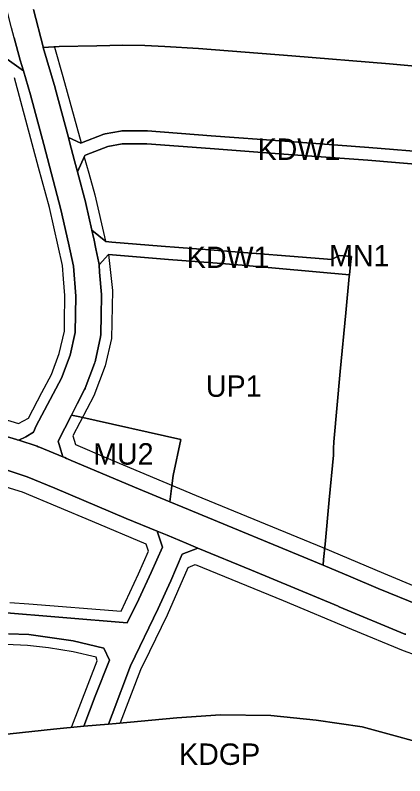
# Model space of a CAD drawing. Extents: x -284239 to -281592, y 34477 to 37267.
# Drawn here: x -282241.7 to -282059.7, y 34820.9 to 35175.9 of the extents above; entities that cross this region are included whole.
import ezdxf

# ---------------------------------------------------------------- set-up
doc = ezdxf.new("R2010")
doc.units = 0
for name, color, linetype in [('linie_rozgraniczajace', 7, 'Continuous'), ('linie_zabudowy_nieprzekraczalne', 7, 'Continuous'), ('oznaczenia_przeznaczen', 7, 'Continuous')]:
    doc.layers.add(name, color=color, linetype=linetype)

msp = doc.modelspace()

# ---------------------------------------------------------------- linework, layer by layer
at = {"layer": 'linie_rozgraniczajace'}
for points in [[(-282213.365, 35044.823), (-282214.504, 35058.766), (-282216.807, 35069.514), (-282220.363, 35085.26), (-282228.359, 35115.489), (-282234.602, 35138.644), (-282237.884, 35149.865), (-282239.35, 35154.875), (-282242.151, 35165.239), (-282243.406, 35170.048), (-282244.814, 35175.442), (-282253.402, 35206.78)], [(-282233.212, 35178.508), (-282228.681, 35161.146), (-282228.584, 35160.813), (-282223.067, 35141.952), (-282223.062, 35141.915), (-282223.032, 35141.829), (-282216.812, 35118.757), (-282216.765, 35118.583), (-282215.519, 35113.873), (-282213.946, 35107.925), (-282212.578, 35102.757), (-282208.734, 35088.223), (-282208.723, 35088.141), (-282208.682, 35088.01), (-282205.872, 35075.568), (-282205.094, 35072.125), (-282205.091, 35072.095), (-282205.08, 35072.06), (-282204.994, 35071.656), (-282203.962, 35066.84), (-282202.632, 35060.366), (-282202.547, 35059.351), (-282202.258, 35055.923), (-282201.38, 35045.499), (-282201.37, 35045.254), (-282201.36, 35045.01), (-282201.372, 35044.951), (-282201.361, 35044.896), (-282201.532, 35035.956), (-282201.703, 35027.017), (-282201.726, 35026.904), (-282201.841, 35025.845), (-282204.403, 35014.173), (-282204.611, 35013.512), (-282204.648, 35013.346), (-282208.975, 35001.845), (-282209.027, 35001.764), (-282209.048, 35001.662), (-282209.286, 35001.155), (-282212.758, 34994.48), (-282215.446, 34989.255), (-282221.696, 34977.104), (-282220.412, 34972.86), (-282219.454, 34969.755), (-282230.319, 34974.29), (-282230.956, 34974.417), (-282231.395, 34974.687), (-282240.01, 34977.492), (-282236.782, 34979.066), (-282233.195, 34981.328), (-282231.835, 34984.166), (-282220.073, 35006.425), (-282216.032, 35017.168), (-282213.689, 35027.839), (-282213.365, 35044.823)], [(-282020.291, 35148.902), (-282066.83, 35153.251), (-282112.459, 35156.95), (-282156.141, 35160.26), (-282171.849, 35161.299), (-282181.065, 35161.688), (-282191.45, 35161.948), (-282203.523, 35161.559), (-282221.178, 35161.299), (-282228.584, 35160.813), (-282228.681, 35161.146), (-282233.212, 35178.508)], [(-282242.151, 35165.239), (-282239.35, 35154.875), (-282237.884, 35149.865), (-282245.473, 35155.402)], [(-282228.584, 35160.813), (-282221.178, 35161.299), (-282203.523, 35161.559), (-282191.45, 35161.948), (-282181.065, 35161.688), (-282171.849, 35161.299), (-282156.141, 35160.26), (-282112.459, 35156.95), (-282066.83, 35153.251), (-282020.291, 35148.902)], [(-282200.25, 35120.291), (-282210.77, 35116.332), (-282210.81, 35116.306), (-282210.862, 35116.296), (-282211.063, 35116.202), (-282216.812, 35118.757), (-282223.032, 35141.829), (-282223.062, 35141.915), (-282223.067, 35141.952), (-282228.584, 35160.813)], [(-282245.473, 35155.402), (-282237.884, 35149.865), (-282234.602, 35138.644), (-282228.359, 35115.489), (-282220.363, 35085.26), (-282216.807, 35069.514), (-282214.504, 35058.766), (-282213.365, 35044.823), (-282213.689, 35027.839), (-282216.032, 35017.168), (-282220.073, 35006.425), (-282231.835, 34984.166), (-282233.195, 34981.328), (-282236.782, 34979.066), (-282240.01, 34977.492), (-282240.721, 34977.723), (-282240.807, 34977.737), (-282241.154, 34977.859), (-282279.01, 34989.12)], [(-282049.199, 35105.852), (-282076.923, 35108.158), (-282116.217, 35111.042), (-282150.666, 35113.587), (-282180.191, 35115.841), (-282191.675, 35115.841), (-282198.383, 35114.583), (-282208.485, 35110.781), (-282209.226, 35110.394), (-282212.578, 35102.757), (-282213.946, 35107.925), (-282215.519, 35113.873), (-282216.765, 35118.583), (-282216.812, 35118.757), (-282211.063, 35116.202), (-282210.862, 35116.296), (-282210.81, 35116.306), (-282210.77, 35116.332), (-282200.25, 35120.291), (-282200.173, 35120.305), (-282199.747, 35120.432), (-282192.507, 35121.789), (-282191.954, 35121.841), (-282180.077, 35121.841), (-282179.951, 35121.816), (-282179.849, 35121.832), (-282150.216, 35119.57), (-282115.776, 35117.025), (-282076.453, 35114.14), (-282045.826, 35111.592)], [(-282045.826, 35111.592), (-282076.453, 35114.14), (-282115.776, 35117.025), (-282150.216, 35119.57), (-282179.849, 35121.832), (-282179.951, 35121.816), (-282180.077, 35121.841), (-282191.954, 35121.841), (-282192.507, 35121.789), (-282199.747, 35120.432), (-282200.173, 35120.305), (-282200.25, 35120.291)], [(-282052.947, 34900.568), (-282072.117, 34908.385), (-282084.848, 34913.748), (-282097.876, 34919.196), (-282097.61, 34921.791), (-282096.959, 34928.967), (-282095.005, 34949.774), (-282093.06, 34970.485), (-282092.956, 34973.664), (-282092.851, 34976.843), (-282089.933, 35009.605), (-282087.293, 35036.946), (-282085.629, 35053.969), (-282085.566, 35054.666), (-282084.825, 35061.116), (-282084.612, 35063.198), (-282090.406, 35063.657), (-282093.791, 35061.82), (-282148.815, 35066.142), (-282173.454, 35068.059), (-282196.546, 35069.972), (-282199.407, 35070.328), (-282205.872, 35075.568), (-282208.682, 35088.01), (-282208.723, 35088.141), (-282208.734, 35088.223), (-282212.578, 35102.757), (-282209.226, 35110.394), (-282208.485, 35110.781), (-282198.383, 35114.583), (-282191.675, 35115.841), (-282180.191, 35115.841), (-282150.666, 35113.587), (-282116.217, 35111.042), (-282076.923, 35108.158), (-282049.199, 35105.852)], [(-282279.01, 34989.12), (-282241.154, 34977.859), (-282240.807, 34977.737), (-282240.721, 34977.723), (-282240.01, 34977.492), (-282231.395, 34974.687), (-282230.956, 34974.417), (-282230.319, 34974.29), (-282219.454, 34969.755), (-282218.565, 34969.384), (-282217.677, 34969.013), (-282217.67, 34969.008), (-282217.212, 34968.816), (-282215.559, 34968.122), (-282184.021, 34954.852), (-282169.412, 34948.765), (-282163.356, 34946.262), (-282097.876, 34919.196)], [(-282245.462, 34963.487), (-282236.047, 34960.422), (-282223.241, 34955.077), (-282189.801, 34941.062), (-282175.432, 34935.114), (-282172.891, 34927.57), (-282178.191, 34915.758), (-282183.993, 34903.266), (-282189.34, 34892.357), (-282249.679, 34897.225)], [(-282059.263, 34886.978), (-282059.691, 34887.063), (-282090.381, 34899.799), (-282090.6, 34899.946), (-282090.856, 34899.997), (-282131.313, 34916.916), (-282156.344, 34927.173), (-282161.857, 34929.432), (-282170.684, 34933.167), (-282175.432, 34935.114), (-282189.801, 34941.062), (-282223.241, 34955.077), (-282236.047, 34960.422), (-282245.462, 34963.487)], [(-282249.679, 34897.225), (-282189.34, 34892.357), (-282183.993, 34903.266), (-282178.191, 34915.758), (-282172.891, 34927.57), (-282175.432, 34935.114), (-282170.684, 34933.167), (-282161.857, 34929.432), (-282156.344, 34927.173), (-282163.629, 34924.341), (-282168.967, 34911.895), (-282169.042, 34911.782), (-282169.068, 34911.661), (-282174.942, 34899.014), (-282174.971, 34898.973), (-282174.98, 34898.935), (-282187.778, 34872.253), (-282196.372, 34849.521), (-282198.128, 34845.058), (-282209.622, 34844.001), (-282204.411, 34858.115), (-282197.628, 34874.895), (-282200.361, 34880.515), (-282214.668, 34883.897), (-282235.321, 34886.807), (-282244.885, 34887.223)], [(-282040.771, 34833.185), (-282079.627, 34843.782), (-282101.068, 34846.832), (-282122.255, 34849.028), (-282145.769, 34849.286), (-282166.182, 34847.995), (-282194.495, 34845.392), (-282198.128, 34845.058), (-282196.372, 34849.521), (-282187.778, 34872.253), (-282174.98, 34898.935), (-282174.971, 34898.973), (-282174.942, 34899.014), (-282169.068, 34911.661), (-282169.042, 34911.782), (-282168.967, 34911.895), (-282163.629, 34924.341), (-282156.344, 34927.173), (-282131.313, 34916.916), (-282090.856, 34899.997), (-282090.6, 34899.946), (-282090.381, 34899.799), (-282059.691, 34887.063), (-282059.263, 34886.978)], [(-282097.876, 34919.196), (-282084.848, 34913.748), (-282072.117, 34908.385), (-282052.947, 34900.568)], [(-282244.885, 34887.223), (-282235.321, 34886.807), (-282214.668, 34883.897), (-282200.361, 34880.515), (-282197.628, 34874.895), (-282204.411, 34858.115), (-282209.622, 34844.001), (-282223.802, 34842.698), (-282254.292, 34839.339)], [(-282551.698, 34795.154), (-282520.433, 34806.265), (-282503.638, 34810.657), (-282492.832, 34812.392), (-282475.474, 34815.179), (-282445.759, 34820.347), (-282406.225, 34823.964), (-282360.49, 34828.615), (-282305.97, 34834.688), (-282271.337, 34837.805), (-282254.292, 34839.339), (-282223.802, 34842.698), (-282209.622, 34844.001), (-282198.128, 34845.058), (-282194.495, 34845.392), (-282166.182, 34847.995), (-282145.769, 34849.286), (-282122.255, 34849.028), (-282101.068, 34846.832), (-282079.627, 34843.782), (-282040.771, 34833.185)]]:
    msp.add_lwpolyline(points, dxfattribs=at)
for points in [[(-282205.872, 35075.568), (-282199.407, 35070.328), (-282196.546, 35069.972), (-282173.454, 35068.059), (-282148.815, 35066.142), (-282093.791, 35061.82), (-282090.406, 35063.657), (-282084.612, 35063.198), (-282084.825, 35061.116), (-282085.566, 35054.666), (-282135.727, 35059.168), (-282149.419, 35060.263), (-282170.109, 35061.873), (-282198.124, 35064.261), (-282202.547, 35059.351), (-282202.632, 35060.366), (-282203.962, 35066.84), (-282204.994, 35071.656), (-282205.08, 35072.06), (-282205.091, 35072.095), (-282205.094, 35072.125)], [(-282215.446, 34989.255), (-282212.758, 34994.48), (-282209.286, 35001.155), (-282209.048, 35001.662), (-282209.027, 35001.764), (-282208.975, 35001.845), (-282204.648, 35013.346), (-282204.611, 35013.512), (-282204.403, 35014.173), (-282201.841, 35025.845), (-282201.726, 35026.904), (-282201.703, 35027.017), (-282201.532, 35035.956), (-282201.361, 35044.896), (-282201.372, 35044.951), (-282201.36, 35045.01), (-282201.37, 35045.254), (-282201.38, 35045.499), (-282202.258, 35055.923), (-282202.547, 35059.351), (-282198.124, 35064.261), (-282170.109, 35061.873), (-282149.419, 35060.263), (-282135.727, 35059.168), (-282085.566, 35054.666), (-282085.629, 35053.969), (-282087.293, 35036.946), (-282089.933, 35009.605), (-282092.851, 34976.843), (-282092.956, 34973.664), (-282093.06, 34970.485), (-282095.005, 34949.774), (-282096.959, 34928.967), (-282097.61, 34921.791), (-282097.876, 34919.196), (-282163.356, 34946.262), (-282169.412, 34948.765), (-282168.676, 34954.917), (-282167.94, 34961.07), (-282164.31, 34977.92), (-282211.5, 34988.38)], [(-282221.696, 34977.104), (-282215.446, 34989.255), (-282211.5, 34988.38), (-282164.31, 34977.92), (-282167.94, 34961.07), (-282168.676, 34954.917), (-282169.412, 34948.765), (-282184.021, 34954.852), (-282215.559, 34968.122), (-282217.212, 34968.816), (-282217.67, 34969.008), (-282217.677, 34969.013), (-282218.565, 34969.384), (-282219.454, 34969.755), (-282220.412, 34972.86)]]:
    msp.add_lwpolyline(points, close=True, dxfattribs=at)
at = {"layer": 'linie_zabudowy_nieprzekraczalne'}
for points in [[(-282223.359, 35160.923), (-282219.522, 35147.297), (-282210.933, 35116.245)], [(-282277.731, 34996.617), (-282240.16, 34985.372), (-282235.53, 34987.885), (-282229.312, 34999.792), (-282224.814, 35008.126), (-282221.11, 35017.982), (-282218.596, 35028.433), (-282218.596, 35032.666), (-282218.464, 35045.102), (-282219.126, 35052.907), (-282219.655, 35059.058), (-282225.608, 35086.178), (-282230.767, 35104.765), (-282242.012, 35146.57)], [(-282209.478, 35109.63), (-282207.352, 35102.186), (-282204.441, 35091.999), (-282199.477, 35070.482)], [(-282198.123, 35064.261), (-282196.239, 35047.351), (-282196.636, 35024.993), (-282199.679, 35012.161), (-282204.97, 34998.204), (-282214.76, 34979.551), (-282213.569, 34975.45), (-282199.017, 34969.364), (-282157.081, 34951.703), (-282097.946, 34927.428), (-282069.636, 34915.522), (-282053.628, 34908.775), (-282035.372, 34902.16), (-282028.954, 34900.342)], [(-282244.261, 34901.829), (-282235.265, 34901.102), (-282192.27, 34897.795), (-282184.068, 34915.125), (-282179.438, 34925.708), (-282180.496, 34929.015), (-282205.632, 34939.533), (-282238.308, 34953.291), (-282272.439, 34963.676)], [(-282157.742, 34919.358), (-282161.049, 34917.903), (-282170.707, 34895.942), (-282179.033, 34878.958), (-282183.147, 34870.3), (-282192.672, 34845.694)], [(-281864.196, 34843.326), (-281870.933, 34843.753), (-281894.481, 34843.621), (-281911.547, 34844.349), (-281932.714, 34845.804), (-281962.215, 34851.691), (-281992.509, 34859.099), (-282026.376, 34868.161), (-282048.204, 34874.908), (-282060.243, 34879.274), (-282084.452, 34889.262), (-282116.335, 34902.623), (-282157.478, 34919.424)], [(-282215.294, 34843.842), (-282203.388, 34874.534), (-282203.917, 34876.253), (-282214.632, 34878.767), (-282226.142, 34880.619), (-282235.931, 34881.677), (-282259.347, 34882.868), (-282288.187, 34883.133), (-282346.395, 34878.767), (-282376.826, 34873.108), (-282394.153, 34870.829), (-282431.455, 34865.663), (-282504.484, 34864.744), (-282524.196, 34864.082), (-282533.059, 34863.156), (-282590.738, 34860.246), (-282607.804, 34856.145), (-282640.745, 34852.308), (-282666.012, 34849.266)]]:
    msp.add_lwpolyline(points, dxfattribs=at)

# ---------------------------------------------------------------- texts
at = {"layer": 'oznaczenia_przeznaczen'}
for s, p in [('KDW1', (-282128.475, 35108.335)), ('KDW1', (-282161.526, 35057.892)), ('MN1', (-282095.066, 35058.651)), ('UP1', (-282152.601, 34997.772)), ('MU2', (-282205.273, 34966.141)), ('KDGP', (-282165.127, 34825.994))]:
    msp.add_text(s, height=10, dxfattribs=at).set_placement(p)

doc.saveas('drawing.dxf')
